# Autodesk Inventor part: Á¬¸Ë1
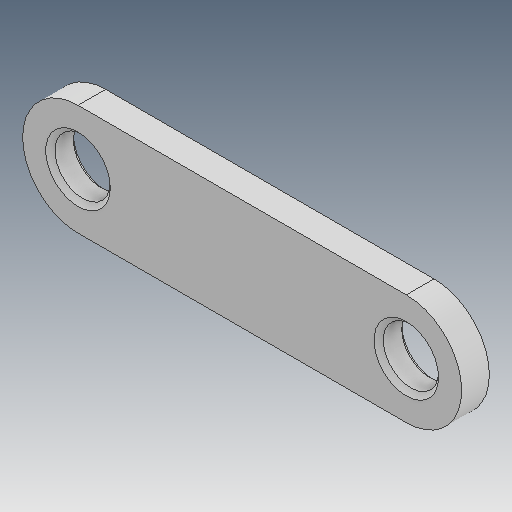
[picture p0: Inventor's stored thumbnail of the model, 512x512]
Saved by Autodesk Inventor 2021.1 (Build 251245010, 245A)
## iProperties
Created: 2013-04
Part Number: Á¬¸Ë1
Material: Ogólny
Document SubType Name: Modeling
Designer: user
Density: 1 g/cm^3
Appearance: Domyślna
Author: user
Revision Number: ÈÎºÎ
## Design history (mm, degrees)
feature "µ¹½Ç1"
node "Bryła1"
